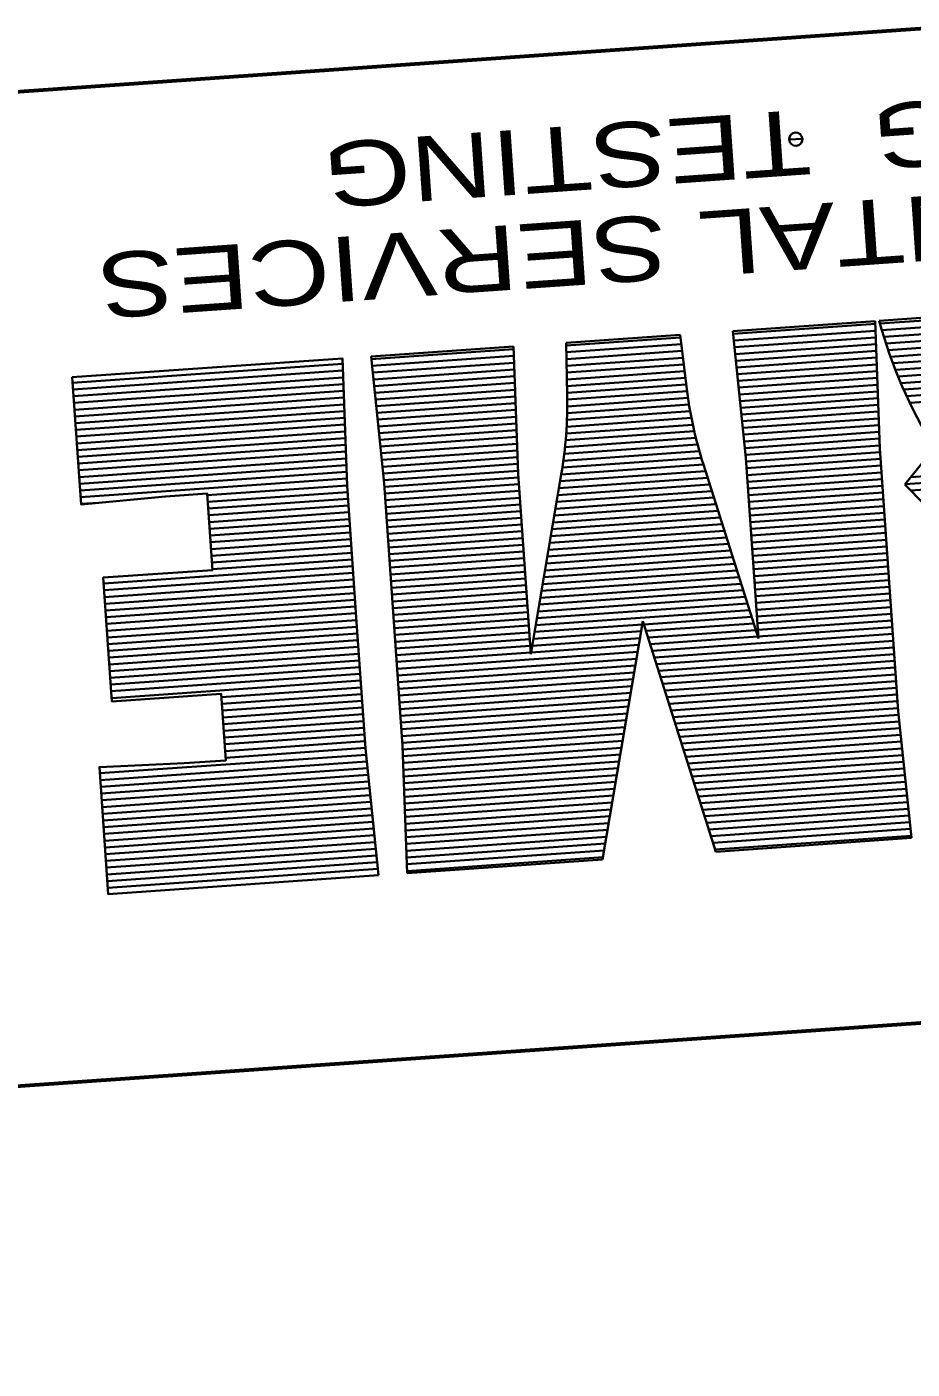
# Model space of a CAD drawing. Extents: x 2399800 to 2400616, y 567347 to 568869.
# Drawn here: x 2400111.3 to 2400147.4, y 568757 to 568811.7 of the extents above; entities that cross this region are included whole.
import ezdxf

# ---------------------------------------------------------------- set-up
doc = ezdxf.new("R2010")
doc.units = 0
doc.header["$LTSCALE"] = 2.4
doc.layers.add('63', color=7, linetype='Continuous', lineweight=35)

msp = doc.modelspace()

# ---------------------------------------------------------------- linework, layer by layer
at = {"layer": '63'}
for p, q in [((2400442.155, 568832.216), (2399943.373, 568797.338)), ((2400142.38, 568807.09), (2400142.646, 568807.108)), ((2400142.646, 568807.108), (2400142.38, 568807.09)), ((2400142.647, 568807.108), (2400142.913, 568807.127)), ((2400142.913, 568807.127), (2400142.647, 568807.108)), ((2400151.499, 568800.091), (2400146.049, 568799.709)), ((2400151.562, 568799.98), (2400146.079, 568799.596)), ((2400145.889, 568799.698), (2400140.076, 568799.292)), ((2400140.076, 568799.292), (2400140.611, 568794.126)), ((2400145.893, 568799.583), (2400140.088, 568799.177)), ((2400145.903, 568799.308), (2400140.116, 568798.904)), ((2400146.078, 568794.508), (2400145.889, 568799.698)), ((2400151.715, 568799.715), (2400146.157, 568799.326)), ((2400151.871, 568799.45), (2400146.238, 568799.056)), ((2400152.029, 568799.185), (2400146.323, 568798.787)), ((2400162.671, 568799.654), (2400146.413, 568798.517)), ((2400162.947, 568799.397), (2400146.507, 568798.248)), ((2400131.146, 568798.667), (2400125.333, 568798.261)), ((2400131.335, 568793.477), (2400131.146, 568798.667)), ((2400137.94, 568799.142), (2400133.282, 568798.817)), ((2400133.282, 568798.817), (2400133.326, 568796.696)), ((2400137.954, 568799.028), (2400133.284, 568798.701)), ((2400137.987, 568798.755), (2400133.29, 568798.426)), ((2400138.192, 568797.037), (2400137.94, 568799.142)), ((2400145.913, 568799.034), (2400140.144, 568798.63)), ((2400145.923, 568798.758), (2400140.173, 568798.356)), ((2400163.191, 568799.139), (2400146.605, 568797.979)), ((2400163.407, 568798.878), (2400146.708, 568797.711)), ((2400125.333, 568798.261), (2400125.868, 568793.095)), ((2400131.15, 568798.552), (2400125.345, 568798.147)), ((2400131.16, 568798.277), (2400125.373, 568797.873)), ((2400138.019, 568798.481), (2400133.296, 568798.151)), ((2400138.052, 568798.208), (2400133.301, 568797.876)), ((2400145.933, 568798.483), (2400140.201, 568798.083)), ((2400145.943, 568798.209), (2400140.229, 568797.809)), ((2400163.598, 568798.616), (2400146.815, 568797.443)), ((2400163.768, 568798.352), (2400146.927, 568797.174)), ((2400163.918, 568798.087), (2400147.043, 568796.907)), ((2400124.175, 568797.956), (2400113.168, 568797.187)), ((2400124.184, 568797.682), (2400113.187, 568796.912)), ((2400131.17, 568798.003), (2400125.401, 568797.599)), ((2400131.18, 568797.728), (2400125.43, 568797.325)), ((2400138.084, 568797.934), (2400133.307, 568797.601)), ((2400138.117, 568797.661), (2400133.313, 568797.325)), ((2400145.953, 568797.934), (2400140.258, 568797.535)), ((2400145.964, 568797.659), (2400140.286, 568797.262)), ((2400164.05, 568797.821), (2400147.164, 568796.64)), ((2400164.164, 568797.553), (2400147.29, 568796.373)), ((2400124.195, 568797.407), (2400113.206, 568796.638)), ((2400124.205, 568797.132), (2400113.225, 568796.364)), ((2400131.19, 568797.453), (2400125.458, 568797.052)), ((2400131.2, 568797.177), (2400125.486, 568796.778)), ((2400138.149, 568797.388), (2400133.319, 568797.05)), ((2400138.182, 568797.115), (2400133.324, 568796.775)), ((2400145.973, 568797.383), (2400140.314, 568796.988)), ((2400145.984, 568797.108), (2400140.343, 568796.714)), ((2400124.215, 568796.856), (2400113.245, 568796.09)), ((2400124.225, 568796.582), (2400113.263, 568795.815)), ((2400131.21, 568796.902), (2400125.515, 568796.504)), ((2400131.22, 568796.628), (2400125.543, 568796.231)), ((2400138.216, 568796.841), (2400133.329, 568796.5)), ((2400138.254, 568796.568), (2400133.329, 568796.224)), ((2400145.993, 568796.834), (2400140.371, 568796.441)), ((2400146.004, 568796.559), (2400140.399, 568796.167)), ((2400124.235, 568796.307), (2400113.283, 568795.541)), ((2400124.245, 568796.032), (2400113.302, 568795.267)), ((2400131.23, 568796.353), (2400125.571, 568795.957)), ((2400131.24, 568796.078), (2400125.6, 568795.683)), ((2400138.343, 568796.023), (2400133.317, 568795.672)), ((2400138.296, 568796.296), (2400133.325, 568795.948)), ((2400146.014, 568796.284), (2400140.428, 568795.893)), ((2400146.024, 568796.009), (2400140.456, 568795.62)), ((2400124.255, 568795.757), (2400113.321, 568794.992)), ((2400124.265, 568795.482), (2400113.34, 568794.718)), ((2400131.25, 568795.803), (2400125.628, 568795.41)), ((2400131.26, 568795.528), (2400125.656, 568795.136)), ((2400138.45, 568795.479), (2400133.287, 568795.118)), ((2400138.394, 568795.751), (2400133.304, 568795.395)), ((2400146.034, 568795.734), (2400140.485, 568795.346)), ((2400146.044, 568795.459), (2400140.513, 568795.072)), ((2400124.275, 568795.207), (2400113.36, 568794.444)), ((2400124.285, 568794.932), (2400113.379, 568794.169)), ((2400131.271, 568795.253), (2400125.685, 568794.862)), ((2400131.28, 568794.978), (2400125.713, 568794.589)), ((2400138.575, 568794.937), (2400133.239, 568794.563)), ((2400138.51, 568795.208), (2400133.265, 568794.841)), ((2400146.054, 568795.184), (2400140.541, 568794.798)), ((2400146.064, 568794.909), (2400140.57, 568794.525)), ((2400124.295, 568794.657), (2400113.398, 568793.895)), ((2400124.305, 568794.382), (2400113.417, 568793.62)), ((2400131.291, 568794.703), (2400125.741, 568794.315)), ((2400131.3, 568794.428), (2400125.769, 568794.041)), ((2400138.718, 568794.395), (2400133.172, 568794.008)), ((2400138.644, 568794.666), (2400133.208, 568794.285)), ((2400146.074, 568794.634), (2400140.598, 568794.251)), ((2400146.089, 568794.359), (2400140.621, 568793.977)), ((2400146.827, 568783.807), (2400146.078, 568794.508)), ((2400148.299, 568794.535), (2400147.09, 568793.04)), ((2400124.315, 568794.107), (2400113.436, 568793.346)), ((2400124.325, 568793.832), (2400113.456, 568793.072)), ((2400131.311, 568794.153), (2400125.798, 568793.767)), ((2400131.32, 568793.878), (2400125.826, 568793.494)), ((2400138.879, 568793.855), (2400133.087, 568793.45)), ((2400138.796, 568794.125), (2400133.132, 568793.729)), ((2400141.125, 568786.775), (2400138.879, 568793.856)), ((2400140.611, 568794.126), (2400141.125, 568786.775)), ((2400146.108, 568794.085), (2400140.64, 568793.703)), ((2400146.127, 568793.811), (2400140.66, 568793.428)), ((2400155.825, 568793.938), (2400147.336, 568793.344)), ((2400124.335, 568793.557), (2400113.475, 568792.797)), ((2400124.345, 568793.282), (2400113.494, 568792.523)), ((2400131.331, 568793.603), (2400125.854, 568793.22)), ((2400131.346, 568793.328), (2400125.878, 568792.946)), ((2400131.849, 568786.126), (2400131.335, 568793.477)), ((2400133.088, 568793.451), (2400131.849, 568786.126)), ((2400139.05, 568793.316), (2400132.993, 568792.892)), ((2400138.965, 568793.586), (2400133.04, 568793.171)), ((2400146.146, 568793.536), (2400140.679, 568793.154)), ((2400146.166, 568793.262), (2400140.698, 568792.88)), ((2400156.05, 568793.677), (2400147.099, 568793.052)), ((2400156.279, 568793.418), (2400147.334, 568792.792)), ((2400124.355, 568793.007), (2400118.659, 568792.609)), ((2400124.374, 568792.733), (2400118.678, 568792.334)), ((2400125.868, 568793.095), (2400126.616, 568782.394)), ((2400131.365, 568793.054), (2400125.897, 568792.672)), ((2400131.384, 568792.78), (2400125.916, 568792.397)), ((2400139.221, 568792.776), (2400132.899, 568792.334)), ((2400139.136, 568793.046), (2400132.946, 568792.613)), ((2400146.185, 568792.988), (2400140.717, 568792.605)), ((2400146.204, 568792.713), (2400140.736, 568792.331)), ((2400147.09, 568793.04), (2400150.428, 568789.646)), ((2400114.226, 568792.299), (2400113.513, 568792.249)), ((2400124.393, 568792.458), (2400118.697, 568792.06)), ((2400124.412, 568792.184), (2400118.717, 568791.786)), ((2400131.403, 568792.505), (2400125.936, 568792.123)), ((2400131.422, 568792.231), (2400125.955, 568791.849)), ((2400139.393, 568792.237), (2400132.805, 568791.776)), ((2400139.307, 568792.507), (2400132.851, 568792.055)), ((2400146.223, 568792.439), (2400140.755, 568792.057)), ((2400146.242, 568792.164), (2400140.775, 568791.782)), ((2400124.431, 568791.91), (2400118.735, 568791.512)), ((2400124.45, 568791.635), (2400118.755, 568791.237)), ((2400131.442, 568791.957), (2400125.974, 568791.574)), ((2400131.461, 568791.682), (2400125.993, 568791.3)), ((2400139.564, 568791.698), (2400132.71, 568791.218)), ((2400139.478, 568791.967), (2400132.757, 568791.497)), ((2400146.262, 568791.89), (2400140.794, 568791.508)), ((2400146.281, 568791.616), (2400140.813, 568791.233)), ((2400124.47, 568791.361), (2400118.774, 568790.963)), ((2400124.489, 568791.087), (2400118.793, 568790.689)), ((2400131.48, 568791.408), (2400126.012, 568791.026)), ((2400131.499, 568791.134), (2400126.032, 568790.751)), ((2400139.735, 568791.158), (2400132.616, 568790.66)), ((2400139.649, 568791.428), (2400132.663, 568790.939)), ((2400146.3, 568791.341), (2400140.832, 568790.959)), ((2400146.319, 568791.067), (2400140.851, 568790.685)), ((2400124.508, 568790.812), (2400118.812, 568790.414)), ((2400124.527, 568790.538), (2400118.831, 568790.14)), ((2400131.518, 568790.859), (2400126.05, 568790.477)), ((2400131.538, 568790.585), (2400126.07, 568790.203)), ((2400139.906, 568790.619), (2400132.521, 568790.103)), ((2400139.82, 568790.889), (2400132.569, 568790.382)), ((2400146.338, 568790.793), (2400140.871, 568790.411)), ((2400146.357, 568790.519), (2400140.89, 568790.136)), ((2400124.547, 568790.264), (2400118.851, 568789.865)), ((2400124.566, 568789.989), (2400118.87, 568789.591)), ((2400131.557, 568790.311), (2400126.089, 568789.928)), ((2400131.576, 568790.036), (2400126.108, 568789.654)), ((2400140.077, 568790.079), (2400132.427, 568789.544)), ((2400139.991, 568790.349), (2400132.474, 568789.824)), ((2400146.377, 568790.244), (2400140.909, 568789.862)), ((2400146.396, 568789.97), (2400140.928, 568789.588)), ((2400124.585, 568789.715), (2400114.436, 568789.005)), ((2400124.604, 568789.441), (2400114.455, 568788.731)), ((2400131.595, 568789.762), (2400126.127, 568789.38)), ((2400131.614, 568789.488), (2400126.146, 568789.105)), ((2400140.248, 568789.54), (2400132.333, 568788.986)), ((2400140.162, 568789.81), (2400132.38, 568789.265)), ((2400146.415, 568789.696), (2400140.947, 568789.313)), ((2400146.434, 568789.421), (2400140.967, 568789.039)), ((2400124.623, 568789.166), (2400114.474, 568788.457)), ((2400124.643, 568788.892), (2400114.493, 568788.182)), ((2400131.633, 568789.213), (2400126.166, 568788.831)), ((2400131.652, 568788.939), (2400126.185, 568788.557)), ((2400140.419, 568789.001), (2400132.238, 568788.429)), ((2400140.333, 568789.27), (2400132.286, 568788.708)), ((2400146.453, 568789.147), (2400140.986, 568788.765)), ((2400146.473, 568788.873), (2400141.005, 568788.49)), ((2400124.661, 568788.618), (2400114.513, 568787.908)), ((2400124.681, 568788.343), (2400114.532, 568787.634)), ((2400131.672, 568788.665), (2400126.204, 568788.282)), ((2400131.691, 568788.39), (2400126.223, 568788.008)), ((2400140.59, 568788.461), (2400132.144, 568787.871)), ((2400140.504, 568788.731), (2400132.191, 568788.15)), ((2400146.492, 568788.598), (2400141.024, 568788.216)), ((2400146.511, 568788.324), (2400141.043, 568787.942)), ((2400124.7, 568788.069), (2400114.551, 568787.359)), ((2400124.719, 568787.795), (2400114.57, 568787.085)), ((2400131.71, 568788.116), (2400126.243, 568787.734)), ((2400131.729, 568787.842), (2400126.262, 568787.459)), ((2400140.761, 568787.922), (2400132.05, 568787.313)), ((2400140.675, 568788.191), (2400132.097, 568787.592)), ((2400146.53, 568788.05), (2400141.062, 568787.667)), ((2400146.549, 568787.775), (2400141.081, 568787.393)), ((2400124.738, 568787.52), (2400114.589, 568786.811)), ((2400124.757, 568787.246), (2400114.608, 568786.536)), ((2400131.749, 568787.568), (2400126.281, 568787.185)), ((2400131.768, 568787.293), (2400126.3, 568786.911)), ((2400136.394, 568787.341), (2400132.003, 568787.034)), ((2400134.775, 568777.762), (2400136.416, 568787.468)), ((2400136.416, 568787.468), (2400139.391, 568778.084)), ((2400140.846, 568787.652), (2400136.455, 568787.345)), ((2400140.932, 568787.383), (2400136.54, 568787.076)), ((2400146.569, 568787.501), (2400141.101, 568787.119)), ((2400146.588, 568787.227), (2400141.12, 568786.844)), ((2400124.777, 568786.972), (2400114.627, 568786.262)), ((2400124.796, 568786.698), (2400114.647, 568785.988)), ((2400131.787, 568787.019), (2400126.319, 568786.637)), ((2400131.806, 568786.745), (2400126.338, 568786.362)), ((2400136.3, 568786.783), (2400131.908, 568786.476)), ((2400136.347, 568787.062), (2400131.956, 568786.755)), ((2400141.018, 568787.113), (2400136.626, 568786.806)), ((2400141.103, 568786.843), (2400136.711, 568786.536)), ((2400146.607, 568786.952), (2400136.797, 568786.266)), ((2400146.626, 568786.678), (2400136.882, 568785.997)), ((2400124.815, 568786.423), (2400114.666, 568785.713)), ((2400124.834, 568786.149), (2400114.685, 568785.439)), ((2400131.825, 568786.47), (2400126.357, 568786.088)), ((2400131.845, 568786.196), (2400126.377, 568785.814)), ((2400136.206, 568786.225), (2400126.396, 568785.539)), ((2400136.253, 568786.504), (2400131.861, 568786.197)), ((2400146.645, 568786.404), (2400136.968, 568785.727)), ((2400146.664, 568786.129), (2400137.053, 568785.457)), ((2400124.854, 568785.875), (2400114.704, 568785.165)), ((2400124.873, 568785.6), (2400114.723, 568784.89)), ((2400136.159, 568785.946), (2400126.415, 568785.265)), ((2400136.112, 568785.667), (2400126.434, 568784.99)), ((2400146.683, 568785.855), (2400137.139, 568785.188)), ((2400146.703, 568785.581), (2400137.225, 568784.918)), ((2400124.892, 568785.326), (2400114.743, 568784.616)), ((2400124.911, 568785.052), (2400114.762, 568784.342)), ((2400136.064, 568785.388), (2400126.453, 568784.716)), ((2400136.017, 568785.109), (2400126.473, 568784.442)), ((2400146.722, 568785.306), (2400137.31, 568784.648)), ((2400146.741, 568785.032), (2400137.396, 568784.378)), ((2400124.93, 568784.777), (2400119.234, 568784.379)), ((2400124.949, 568784.503), (2400119.254, 568784.105)), ((2400135.97, 568784.83), (2400126.492, 568784.167)), ((2400135.923, 568784.551), (2400126.511, 568783.893)), ((2400146.76, 568784.758), (2400137.481, 568784.109)), ((2400146.78, 568784.483), (2400137.567, 568783.839)), ((2400124.968, 568784.228), (2400119.273, 568783.83)), ((2400124.988, 568783.954), (2400119.292, 568783.556)), ((2400135.876, 568784.272), (2400126.53, 568783.619)), ((2400135.828, 568783.993), (2400126.549, 568783.345)), ((2400146.799, 568784.209), (2400137.652, 568783.569)), ((2400146.818, 568783.935), (2400137.737, 568783.3)), ((2400125.007, 568783.68), (2400119.311, 568783.282)), ((2400125.026, 568783.405), (2400119.33, 568783.007)), ((2400135.782, 568783.714), (2400126.569, 568783.07)), ((2400135.734, 568783.435), (2400126.588, 568782.796)), ((2400146.842, 568783.661), (2400137.823, 568783.03)), ((2400146.87, 568783.387), (2400137.909, 568782.76)), ((2400147.362, 568778.642), (2400146.827, 568783.807)), ((2400125.045, 568783.131), (2400119.35, 568782.733)), ((2400125.064, 568782.857), (2400119.369, 568782.459)), ((2400135.687, 568783.157), (2400126.607, 568782.522)), ((2400135.64, 568782.878), (2400126.621, 568782.247)), ((2400146.899, 568783.113), (2400137.994, 568782.491)), ((2400146.927, 568782.84), (2400138.08, 568782.221)), ((2400125.084, 568782.583), (2400119.388, 568782.184)), ((2400125.103, 568782.308), (2400119.407, 568781.91)), ((2400126.616, 568782.394), (2400126.805, 568777.204)), ((2400135.593, 568782.598), (2400126.631, 568781.972)), ((2400135.546, 568782.319), (2400126.641, 568781.697)), ((2400146.955, 568782.566), (2400138.165, 568781.951)), ((2400146.984, 568782.292), (2400138.251, 568781.682)), ((2400125.13, 568782.035), (2400114.28, 568781.276)), ((2400125.159, 568781.761), (2400114.3, 568781.001)), ((2400135.499, 568782.041), (2400126.651, 568781.422)), ((2400135.451, 568781.762), (2400126.661, 568781.147)), ((2400147.012, 568782.019), (2400138.336, 568781.412)), ((2400147.04, 568781.745), (2400138.422, 568781.142)), ((2400125.187, 568781.487), (2400114.319, 568780.727)), ((2400125.215, 568781.213), (2400114.338, 568780.453)), ((2400135.404, 568781.483), (2400126.672, 568780.872)), ((2400135.357, 568781.204), (2400126.681, 568780.597)), ((2400147.069, 568781.471), (2400138.507, 568780.873)), ((2400147.097, 568781.198), (2400138.593, 568780.603)), ((2400125.244, 568780.939), (2400114.357, 568780.178)), ((2400125.272, 568780.666), (2400114.376, 568779.904)), ((2400135.31, 568780.925), (2400126.692, 568780.322)), ((2400135.263, 568780.646), (2400126.701, 568780.047)), ((2400147.125, 568780.924), (2400138.678, 568780.333)), ((2400147.154, 568780.65), (2400138.764, 568780.064)), ((2400125.3, 568780.392), (2400114.396, 568779.63)), ((2400125.329, 568780.118), (2400114.414, 568779.355)), ((2400135.215, 568780.367), (2400126.712, 568779.772)), ((2400135.169, 568780.088), (2400126.721, 568779.497)), ((2400147.182, 568780.377), (2400138.85, 568779.794)), ((2400147.21, 568780.103), (2400138.935, 568779.524)), ((2400125.357, 568779.845), (2400114.434, 568779.081)), ((2400125.385, 568779.571), (2400114.453, 568778.807)), ((2400135.121, 568779.809), (2400126.732, 568779.222)), ((2400135.074, 568779.53), (2400126.742, 568778.947)), ((2400147.238, 568779.829), (2400139.021, 568779.255)), ((2400147.267, 568779.555), (2400139.106, 568778.985)), ((2400125.414, 568779.297), (2400114.472, 568778.532)), ((2400125.442, 568779.024), (2400114.491, 568778.258)), ((2400135.027, 568779.251), (2400126.752, 568778.672)), ((2400134.98, 568778.972), (2400126.762, 568778.397)), ((2400147.295, 568779.282), (2400139.192, 568778.715)), ((2400147.323, 568779.008), (2400139.277, 568778.445)), ((2400125.47, 568778.75), (2400114.51, 568777.984)), ((2400125.499, 568778.476), (2400114.53, 568777.709)), ((2400134.933, 568778.693), (2400126.772, 568778.122)), ((2400134.885, 568778.414), (2400126.782, 568777.847)), ((2400147.352, 568778.734), (2400139.362, 568778.176)), ((2400139.391, 568778.084), (2400147.362, 568778.642)), ((2400125.527, 568778.203), (2400114.549, 568777.435)), ((2400125.555, 568777.929), (2400114.568, 568777.161)), ((2400134.838, 568778.135), (2400126.792, 568777.572)), ((2400134.791, 568777.856), (2400126.802, 568777.297)), ((2400125.584, 568777.655), (2400114.587, 568776.887)), ((2400125.612, 568777.382), (2400114.606, 568776.612)), ((2400126.805, 568777.204), (2400134.775, 568777.762))]:
    msp.add_line(p, q, dxfattribs=at)
at = {"layer": '63', "lineweight": 60}
msp.add_lwpolyline([(2400444.975, 568791.882), (2399946.193, 568757.004), (2399943.373, 568797.338), (2400442.155, 568832.216)], close=True, dxfattribs=at)
at = {"layer": '63'}
msp.add_lwpolyline([(2400125.639, 568777.123), (2400125.104, 568782.289), (2400124.744, 568787.437), (2400124.356, 568792.989), (2400124.166, 568798.179), (2400113.152, 568797.409), (2400113.514, 568792.231), (2400116.96, 568792.559), (2400118.654, 568792.677), (2400118.872, 568789.558), (2400114.419, 568789.247), (2400114.595, 568786.727), (2400114.771, 568784.208), (2400119.225, 568784.519), (2400119.414, 568781.804), (2400117.72, 568781.686), (2400114.263, 568781.53), (2400114.624, 568776.352)], close=True, dxfattribs=at)
for centre, radius, start, end in [((2400142.647, 568807.108), 0.268, 4, 184), ((2400142.647, 568807.108), 0.268, 184, 4), ((2400142.647, 568807.108), 0.0003, 4, 184), ((2400142.647, 568807.108), 0.0003, 184, 4), ((2400164.772, 568804.775), 19.397, 195.1384, 211.8654), ((2400155.372, 568799.087), 17.302, 186.8042, 197.595), ((2400116.028, 568796.335), 17.302, 350.405, 1.1958)]:
    msp.add_arc(centre, radius, start, end, dxfattribs=at)

# ---------------------------------------------------------------- texts
at = {"layer": '63', "width": 1.3}
for s, p in [('ENGINEERING  TESTING', (2400177.739, 568810.742)), ('ENVIRONMENTAL SERVICES', (2400178.008, 568806.899))]:
    msp.add_text(s, height=2.64, rotation=184, dxfattribs=at).set_placement(p)

doc.saveas('drawing.dxf')
